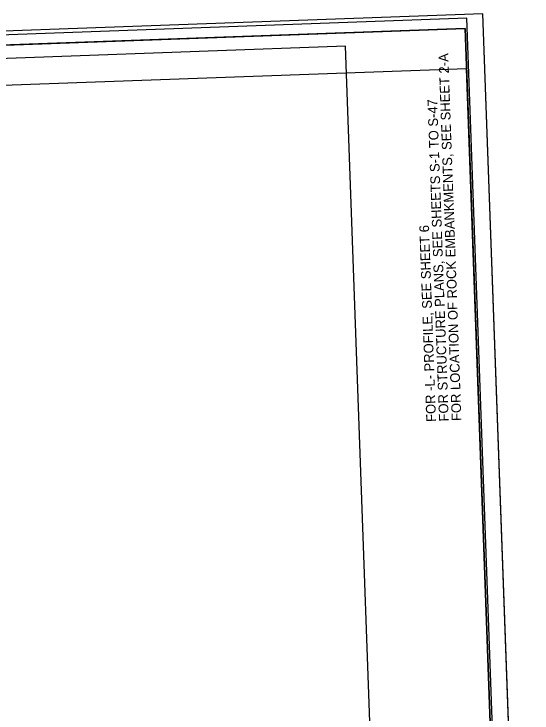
# Model space of a CAD drawing. Extents: x 2065256 to 2066537, y 145527 to 147314.
# Drawn here: x 2065896 to 2066537, y 146420 to 147284 of the extents above; entities that cross this region are included whole.
import ezdxf

# ---------------------------------------------------------------- set-up
doc = ezdxf.new("R2010")
doc.units = 0
for name, color, linetype in [('Prop Dimension', 7, 'Continuous'), ('Sheet Clip Boundary CELL', 7, 'Continuous'), ('Sheet Cutting Line CELL', 7, 'Continuous'), ('Sheet Layout Plan Border', 7, 'Continuous'), ('Sheet Plan CELL', 7, 'Continuous'), ('Sheet Plan Layout CELL', 7, 'Continuous'), ('Sheet Plot Border Inside CELL', 7, 'Continuous'), ('Sheet Plot Border Outside CELL', 7, 'Continuous')]:
    doc.layers.add(name, color=color, linetype=linetype)

msp = doc.modelspace()

# ---------------------------------------------------------------- linework, layer by layer
at = {"layer": 'Sheet Clip Boundary CELL'}
msp.add_lwpolyline([(2066225.3, 145855.32), (2066356.28, 145860.05), (2066306.24, 147244.42), (2065582.18, 147218.25), (2065589.94, 147003.52), (2065566.99, 147001.07), (2065609.27, 145831.43)], close=True, dxfattribs=at)
at = {"layer": 'Sheet Cutting Line CELL'}
msp.add_line((2066537.03, 145601.88), (2066476.21, 147284.29), dxfattribs=at)
at = {"layer": 'Sheet Layout Plan Border'}
msp.add_lwpolyline([(2066506.71, 145817.42), (2066456.14, 147216.52), (2065618.17, 147186.22), (2065625.01, 146997.09), (2065413.66, 146989.45), (2065457.4, 145779.49)], close=True, dxfattribs=at)
at = {"layer": 'Sheet Plan CELL'}
for points in [[(2065405.01, 147228.58), (2065459.2, 145729.52), (2066508.52, 145767.45), (2066454.33, 147266.48)], [(2066508.52, 145767.45), (2065459.23, 145729.49), (2065412.23, 147028.63), (2065562.19, 147034.07), (2065554.98, 147233.97), (2066454.33, 147266.48)]]:
    msp.add_lwpolyline(points, close=True, dxfattribs=at)
at = {"layer": 'Sheet Plan Layout CELL'}
msp.add_lwpolyline([(2065459.23, 145729.49), (2066508.52, 145767.45), (2066454.33, 147266.47), (2065616.37, 147236.18), (2065625.01, 146997.09), (2065413.66, 146989.45)], close=True, dxfattribs=at)
at = {"layer": 'Sheet Plot Border Inside CELL'}
msp.add_lwpolyline([(2066516.57, 145614.15), (2066456.38, 147279.05), (2065402.08, 147240.95), (2065462.26, 145576.04)], close=True, dxfattribs=at)
at = {"layer": 'Sheet Plot Border Outside CELL'}
msp.add_lwpolyline([(2066537.03, 145601.88), (2066476.21, 147284.29), (2065381.93, 147244.73), (2065442.74, 145562.33)], close=True, dxfattribs=at)

# ---------------------------------------------------------------- texts
at = {"layer": 'Prop Dimension'}
for s, p in [('FOR LOCATION OF ROCK EMBANKMENTS, SEE SHEET 2-A ', (2066449.78, 146781.42)), ('FOR STRUCTURE PLANS, SEE SHEETS S-1 TO S-47', (2066434.06, 146780.86)), ('FOR -L- PROFILE, SEE SHEET 6', (2066418.34, 146780.29))]:
    msp.add_text(s, height=12, rotation=92.07024, dxfattribs=at).set_placement(p)

doc.saveas('drawing.dxf')
